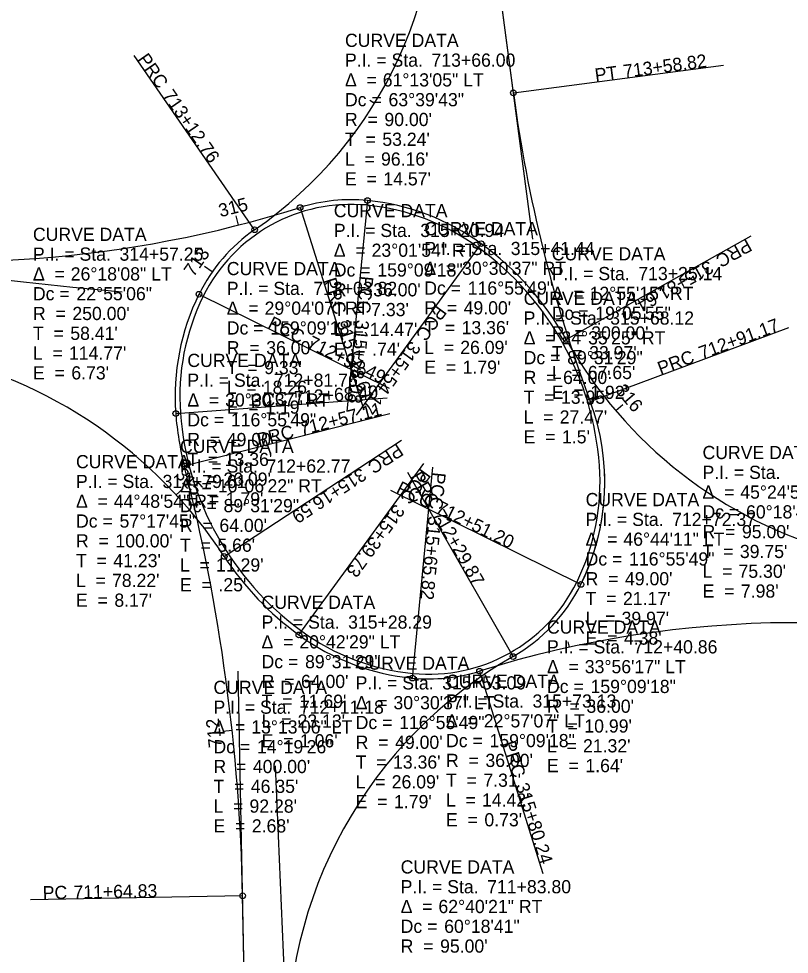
# Model space of a CAD drawing. Extents: x 2047151 to 2048731, y 456453 to 457874.
# Drawn here: x 2047586.9 to 2047750.5, y 456908.9 to 457107.4 of the extents above; entities that cross this region are included whole.
import ezdxf

# ---------------------------------------------------------------- set-up
doc = ezdxf.new("R2010")
doc.units = 0
for name, color, linetype in [('GE_P_Alignment', 7, 'Continuous'), ('GE_P_Alignment_100_Cardinal_Points', 7, 'Continuous'), ('GE_P_Alignment_100_Curve_Data', 7, 'Continuous'), ('GE_P_Alignment_100_Stations', 7, 'Continuous'), ('GE_P_Alignment_500_Cardinal_Points', 7, 'Continuous'), ('GE_P_Alignment_500_Curve_Data', 7, 'Continuous'), ('GE_P_Alignment_500_Stations', 7, 'Continuous')]:
    doc.layers.add(name, color=color, linetype=linetype)

msp = doc.modelspace()

# ---------------------------------------------------------------- linework, layer by layer
at = {"layer": 'GE_P_Alignment'}
for p, q in [((2047696.03, 457060.66), (2047679.37, 457186.67)), ((2047691.92, 457091.7), (2047681.74, 457168.72)), ((2047710.2, 457012.61), (2047710.2, 457012.61)), ((2047643.48, 456456.55), (2047633.52, 456968.93)), ((2047648.82, 456775.95), (2047641.42, 456948.9)), ((2047643.48, 456456.55), (2047634.45, 456921.29))]:
    msp.add_line(p, q, dxfattribs=at)
for centre, radius, start, end in [((2047585.83, 457136.69), 90, 304.6468, 5.8647), ((2047585.83, 457136.69), 90, 304.6468, 5.8647), ((2047717.44, 458244.57), 1200, 248.79098, 264.8083), ((2047989.34, 457131.02), 300, 187.5309, 200.4517), ((2047989.34, 457131.02), 300, 187.5309, 200.4517), ((2047571.6, 457305.84), 250, 261.1691, 287.4713), ((2047571.6, 457305.84), 250, 261.1691, 287.4713), ((2047657.47, 457033.03), 35, 84.4396, 153.7154), ((2047657.47, 457033.03), 36, 84.4396, 107.4713), ((2047657.47, 457033.03), 36, 84.4396, 107.4713), ((2047657.47, 457033.03), 36, 84.4396, 107.4713), ((2047656.21, 457020.09), 48, 53.9294, 84.4396), ((2047656.21, 457020.09), 49, 53.9294, 84.4396), ((2047656.21, 457020.09), 49, 53.9294, 84.4396), ((2047656.21, 457020.09), 49, 53.9294, 84.4396), ((2047657.47, 457033.03), 36, 124.6468, 153.7154), ((2047657.47, 457033.03), 36, 124.6468, 153.7154), ((2047657.47, 457033.03), 36, 124.6468, 153.7154), ((2047647.37, 457007.97), 64, 29.339, 53.9294), ((2047647.37, 457007.97), 64, 29.339, 53.9294), ((2047647.37, 457007.97), 64, 29.339, 53.9294), ((2047647.37, 457007.97), 63, 4.2256, 53.9294), ((2047669.12, 457027.27), 49, 153.7154, 184.2256), ((2047669.12, 457027.27), 49, 153.7154, 184.2256), ((2047669.12, 457027.27), 49, 153.7154, 184.2256), ((2047669.12, 457027.27), 48, 153.7154, 184.2256), ((2047785.98, 457085.87), 95, 209.339, 254.7532), ((2047785.98, 457085.87), 95, 209.339, 254.7532), ((2047546.89, 456938.53), 100, 33.2214, 78.0363), ((2047546.89, 456938.53), 100, 33.2214, 78.0363), ((2047662.33, 457009.07), 49, 333.7154, 20.4517), ((2047662.33, 457009.07), 49, 333.7154, 20.4517), ((2047684.08, 457028.38), 64, 184.2256, 194.3318), ((2047684.08, 457028.38), 64, 184.2256, 194.3318), ((2047684.08, 457028.38), 64, 184.2256, 194.3318), ((2047684.08, 457028.38), 63, 184.2256, 233.9294), ((2047234.52, 456913.52), 400, 1.1135, 14.3318), ((2047234.52, 456913.52), 400, 1.1135, 14.3318), ((2047662.33, 457009.07), 48, 333.7154, 4.2256), ((2047662.33, 457009.07), 49, 333.7154, 3.079), ((2047684.08, 457028.38), 64, 213.2214, 233.9294), ((2047684.08, 457028.38), 64, 213.2214, 233.9294), ((2047684.08, 457028.38), 64, 213.2214, 233.9294), ((2047673.99, 457003.32), 35, 264.4396, 333.7154), ((2047673.99, 457003.32), 36, 299.7772, 333.7154), ((2047673.99, 457003.32), 36, 299.7772, 333.7154), ((2047673.99, 457003.32), 36, 299.7772, 333.7154), ((2047752, 456754.25), 225, 73.2611, 107.3917), ((2047752, 456754.25), 225, 73.2611, 107.3917), ((2047675.25, 457016.25), 49, 233.9294, 264.4396), ((2047675.25, 457016.25), 49, 233.9294, 264.4396), ((2047675.25, 457016.25), 49, 233.9294, 264.4396), ((2047675.25, 457016.25), 48, 233.9294, 264.4396), ((2047739.05, 456889.61), 95, 119.7772, 182.4498), ((2047739.05, 456889.61), 95, 119.7772, 182.4498), ((2047673.99, 457003.32), 36, 264.4396, 287.3917), ((2047673.99, 457003.32), 36, 264.4396, 287.3917), ((2047673.99, 457003.32), 36, 264.4396, 287.3407)]:
    msp.add_arc(centre, radius, start, end, dxfattribs=at)
at = {"layer": 'GE_P_Alignment_100_Cardinal_Points'}
for p, q in [((2047637, 457062.65), (2047611.42, 457099.67)), ((2047646.66, 457067.37), (2047660.17, 457024.45)), ((2047660.95, 457068.86), (2047656.59, 457024.07)), ((2047703.17, 457039.33), (2047742.39, 457061.37)), ((2047685.06, 457059.7), (2047658.56, 457023.32)), ((2047625.19, 457048.97), (2047665.54, 457029.04)), ((2047620.26, 457023.66), (2047665.13, 457026.98)), ((2047622.07, 457012.54), (2047665.67, 457023.68)), ((2047634.45, 456921.29), (2047589.45, 456920.42))]:
    msp.add_line(p, q, dxfattribs=at)
for centre in [(2047660.95, 457068.86), (2047646.66, 457067.37), (2047637, 457062.65), (2047685.06, 457059.7), (2047625.19, 457048.97), (2047703.17, 457039.33), (2047620.26, 457023.66), (2047622.07, 457012.54), (2047634.45, 456921.29)]:
    msp.add_circle(centre, 0.6, dxfattribs=at)
at = {"layer": 'GE_P_Alignment_100_Stations'}
for p, q in [((2047662.45, 457089.47), (2047661.43, 457090.1)), ((2047633.57, 457063.64), (2047633.08, 457065.58)), ((2047681.59, 457062.01), (2047682.21, 457063.03)), ((2047628, 457053.71), (2047626.36, 457054.85)), ((2047713.65, 457024.29), (2047715.17, 457025.58)), ((2047623.77, 457005.63), (2047622.6, 457005.36)), ((2047632.22, 456956.38), (2047630.23, 456956.17))]:
    msp.add_line(p, q, dxfattribs=at)
at = {"layer": 'GE_P_Alignment_500_Cardinal_Points'}
for p, q in [((2047691.92, 457091.7), (2047736.54, 457097.6)), ((2047708.25, 457026.19), (2047750.41, 457041.92)), ((2047630.54, 456993.31), (2047668.19, 457017.97)), ((2047646.4, 456976.65), (2047672.89, 457013.02)), ((2047670.5, 456967.48), (2047674.86, 457012.27)), ((2047691.87, 456972.07), (2047669.52, 457011.13)), ((2047706.27, 456987.37), (2047665.92, 457007.3)), ((2047684.75, 456968.96), (2047698.2, 456926.02))]:
    msp.add_line(p, q, dxfattribs=at)
for centre in [(2047691.92, 457091.7), (2047708.25, 457026.19), (2047630.54, 456993.31), (2047706.27, 456987.37), (2047646.4, 456976.65), (2047691.87, 456972.07), (2047670.5, 456967.48), (2047684.75, 456968.96)]:
    msp.add_circle(centre, 0.6, dxfattribs=at)
at = {"layer": 'GE_P_Alignment_500_Stations'}
for p, q in [((2047705.28, 457034.52), (2047704.14, 457034.13)), ((2047620.34, 457006.38), (2047621.81, 457007.74)), ((2047703.84, 456974.03), (2047703.59, 456975.2)), ((2047668.68, 456953.43), (2047667.79, 456954.24))]:
    msp.add_line(p, q, dxfattribs=at)

# ---------------------------------------------------------------- texts
at = {"layer": 'GE_P_Alignment_100_Cardinal_Points'}
for s, rotation, p in [('PRC', 304.6468, (2047612.03, 457098.86)), ('713+12.76', 304.6468, (2047617.34, 457091.17)), ('PRC', 209.339, (2047741.5, 457060.82)), ('315+81.64', 209.339, (2047733.35, 457056.24)), ('PRC', 287.4713, (2047651.56, 457051.95)), ('PCC', 264.4396, (2047659.45, 457052.92)), ('PCC', 233.9294, (2047675.7, 457046.78)), ('PCC', 333.7154, (2047639.59, 457041.91)), ('315+13.61', 287.4713, (2047654.37, 457043.03)), ('315+28.08', 264.4396, (2047658.54, 457043.61)), ('712+94.49', 333.7154, (2047647.97, 457037.77)), ('315+54.17', 233.9294, (2047670.2, 457039.22)), ('712+68.40', 4.2256, (2047645.54, 457025.58)), ('PCC', 4.2256, (2047636.22, 457024.89)), ('712+57.11', 14.3318, (2047646.94, 457018.94)), ('PRC', 14.3318, (2047637.88, 457016.62)), ('PC', 1.1135, (2047592.04, 456920.52)), ('711+64.83', 1.1135, (2047598.56, 456920.64))]:
    msp.add_text(s, height=2.8, rotation=rotation, dxfattribs=at).set_placement(p)
at = {"layer": 'GE_P_Alignment_100_Curve_Data'}
for s, p in [('CURVE DATA', (2047656.18, 457101.46)), ('P.I. = Sta. ', (2047656.18, 457097.26)), ('713+66.00', (2047674.55, 457097.26)), ('Δ  = ', (2047656.18, 457093.06)), ('61°13\'05" LT', (2047664.2, 457093.06)), ('Dc = ', (2047656.18, 457088.86)), ('63°39\'43"', (2047665.42, 457088.86)), ('R  = ', (2047656.18, 457084.66)), ("90.00'", (2047664.55, 457084.66)), ('T  = ', (2047656.18, 457080.46)), ("53.24'", (2047664.11, 457080.46)), ('L  = ', (2047656.18, 457076.26)), ("96.16'", (2047663.83, 457076.26)), ('E  = ', (2047656.18, 457072.06)), ("14.57'", (2047664.33, 457072.06)), ('CURVE DATA', (2047653.81, 457065.31)), ('P.I. = Sta. ', (2047653.81, 457061.11)), ('315+20.94', (2047672.17, 457061.11)), ('CURVE DATA', (2047673.01, 457061.48)), ('CURVE DATA', (2047589.94, 457060.28)), ('Δ  = ', (2047653.81, 457056.91)), ('23°01\'54" RT', (2047661.83, 457056.91)), ('P.I. = Sta. ', (2047673.01, 457057.28)), ('315+41.44', (2047691.37, 457057.28)), ('P.I. = Sta. ', (2047589.94, 457056.08)), ('314+57.25', (2047608.31, 457056.08)), ('CURVE DATA', (2047631.09, 457053.01)), ('Dc = ', (2047653.81, 457052.71)), ('159°09\'18"', (2047663.05, 457052.71)), ('Δ  = ', (2047673.01, 457053.08)), ('30°30\'37" RT', (2047681.03, 457053.08)), ('Δ  = ', (2047589.94, 457051.88)), ('26°18\'08" LT', (2047597.96, 457051.88)), ('P.I. = Sta. ', (2047631.09, 457048.81)), ('713+03.82', (2047649.46, 457048.81)), ('R  = ', (2047653.81, 457048.51)), ("36.00'", (2047662.17, 457048.51)), ('Dc = ', (2047673.01, 457048.88)), ('116°55\'49"', (2047682.24, 457048.88)), ('Dc = ', (2047589.94, 457047.68)), ('22°55\'06"', (2047599.18, 457047.68)), ('CURVE DATA', (2047694.11, 457046.71)), ('Δ  = ', (2047631.09, 457044.61)), ('29°04\'07" RT', (2047639.12, 457044.61)), ('R  = ', (2047673.01, 457044.68)), ("49.00'", (2047681.37, 457044.68)), ('R  = ', (2047589.94, 457043.48)), ("250.00'", (2047598.31, 457043.48)), ('T  = ', (2047653.81, 457044.31)), ("7.33'", (2047661.74, 457044.31)), ('P.I. = Sta. ', (2047694.11, 457042.51)), ('315+68.12', (2047712.48, 457042.51)), ("13.36'", (2047680.94, 457040.48)), ('T  = ', (2047589.94, 457039.28)), ("58.41'", (2047597.87, 457039.28)), ('Dc = ', (2047631.09, 457040.41)), ('159°09\'18"', (2047640.33, 457040.41)), ('L  = ', (2047653.81, 457040.11)), ("14.47'", (2047661.45, 457040.11)), ('T  = ', (2047673.01, 457040.48)), ('Δ  = ', (2047694.11, 457038.31)), ('24°35\'25" RT', (2047702.13, 457038.31)), ('L  = ', (2047589.94, 457035.08)), ("114.77'", (2047597.59, 457035.08)), ('R  = ', (2047631.09, 457036.21)), ("36.00'", (2047639.46, 457036.21)), ('E  = ', (2047653.81, 457035.91)), (".74'", (2047661.96, 457035.91)), ('L  = ', (2047673.01, 457036.28)), ("26.09'", (2047680.65, 457036.28)), ('CURVE DATA', (2047622.72, 457033.52)), ('Dc = ', (2047694.11, 457034.11)), ('89°31\'29"', (2047703.35, 457034.11)), ('E  = ', (2047589.94, 457030.88)), ("6.73'", (2047598.09, 457030.88)), ('T  = ', (2047631.09, 457032.01)), ("9.33'", (2047639.03, 457032.01)), ('E  = ', (2047673.01, 457032.08)), ("1.79'", (2047681.16, 457032.08)), ('P.I. = Sta. ', (2047622.72, 457029.32)), ('712+81.76', (2047641.09, 457029.32)), ('R  = ', (2047694.11, 457029.91)), ("64.00'", (2047702.48, 457029.91)), ('L  = ', (2047631.09, 457027.81)), ("18.26'", (2047638.74, 457027.81)), ('Δ  = ', (2047622.72, 457025.12)), ('30°30\'37" RT', (2047630.74, 457025.12)), ('T  = ', (2047694.11, 457025.71)), ("13.95'", (2047702.04, 457025.71)), ('E  = ', (2047631.09, 457023.61)), ("1.19'", (2047639.25, 457023.61)), ('Dc = ', (2047622.72, 457020.92)), ('116°55\'49"', (2047631.96, 457020.92)), ('L  = ', (2047694.11, 457021.51)), ("27.47'", (2047701.76, 457021.51)), ('R  = ', (2047622.72, 457016.72)), ("49.00'", (2047631.09, 457016.72)), ('E  = ', (2047694.11, 457017.31)), ("1.5'", (2047702.26, 457017.31)), ('CURVE DATA', (2047621.16, 457015.3)), ('CURVE DATA', (2047732.08, 457013.97)), ('P.I. = Sta. ', (2047621.16, 457011.1)), ('T  = ', (2047622.72, 457012.52)), ("13.36'", (2047630.65, 457012.52)), ('712+62.77', (2047639.53, 457011.1)), ('P.I. = Sta. ', (2047732.08, 457009.77)), ('Δ  = ', (2047621.16, 457006.9)), ('L  = ', (2047622.72, 457008.32)), ('10°06\'22" RT', (2047629.19, 457006.9)), ("26.09'", (2047630.37, 457008.32)), ('Δ  = ', (2047732.08, 457005.57)), ('45°24\'51" LT', (2047740.1, 457005.57)), ('E  = ', (2047622.72, 457004.12)), ("1.79'", (2047630.87, 457004.12)), ('Dc = ', (2047621.16, 457002.7)), ('89°31\'29"', (2047630.4, 457002.7)), ('Dc = ', (2047732.08, 457001.37)), ('60°18\'41"', (2047741.32, 457001.37)), ('R  = ', (2047621.16, 456998.5)), ("64.00'", (2047629.53, 456998.5)), ('R  = ', (2047732.08, 456997.17)), ("95.00'", (2047740.45, 456997.17)), ('T  = ', (2047621.16, 456994.3)), ("5.66'", (2047629.1, 456994.3)), ('T  = ', (2047732.08, 456992.97)), ("39.75'", (2047740.01, 456992.97)), ('L  = ', (2047621.16, 456990.1)), ("11.29'", (2047628.81, 456990.1)), ('L  = ', (2047732.08, 456988.77)), ("75.30'", (2047739.73, 456988.77)), ('E  = ', (2047621.16, 456985.9)), (".25'", (2047629.32, 456985.9)), ('E  = ', (2047732.08, 456984.57)), ("7.98'", (2047740.23, 456984.57)), ('CURVE DATA', (2047628.26, 456964.12)), ('P.I. = Sta. ', (2047628.26, 456959.92)), ('712+11.18', (2047646.63, 456959.92)), ('Δ  = ', (2047628.26, 456955.72)), ('13°13\'06" LT', (2047636.28, 456955.72)), ('Dc = ', (2047628.26, 456951.52)), ('14°19\'26"', (2047637.5, 456951.52)), ('R  = ', (2047628.26, 456947.32)), ("400.00'", (2047636.63, 456947.32)), ('T  = ', (2047628.26, 456943.12)), ("46.35'", (2047636.19, 456943.12)), ('L  = ', (2047628.26, 456938.92)), ("92.28'", (2047635.91, 456938.92)), ('E  = ', (2047628.26, 456934.72)), ("2.68'", (2047636.41, 456934.72))]:
    msp.add_text(s, height=2.8, dxfattribs=at).set_placement(p)
at = {"layer": 'GE_P_Alignment_100_Stations'}
for s, rotation, p in [('315', 14.3528, (2047629.75, 457065.29)), ('713', 54.9481, (2047624.04, 457052.5)), ('316', 310.4129, (2047713.46, 457028.44)), ('712', 96.1514, (2047630.08, 456952.86))]:
    msp.add_text(s, height=2.8, rotation=rotation, dxfattribs=at).set_placement(p)
at = {"layer": 'GE_P_Alignment_500_Cardinal_Points'}
for s, rotation, p in [('713+58.82', 7.5309, (2047715.45, 457094.86)), ('PT', 7.5309, (2047709.41, 457094.06)), ('712+91.17', 20.4517, (2047731.94, 457035.08)), ('PRC', 20.4517, (2047723.18, 457031.81)), ('PRC', 213.2214, (2047667.34, 457017.36)), ('315+16.59', 213.2214, (2047659.52, 457012.24)), ('PCC', 233.9294, (2047672.33, 457012.16)), ('PRC', 299.7772, (2047670.03, 457010.32)), ('PCC', 264.4396, (2047674.81, 457011.26)), ('PCC', 333.7154, (2047666.85, 457006.89)), ('315+39.73', 233.9294, (2047666.82, 457004.61)), ('712+51.20', 333.7154, (2047675.23, 457002.76)), ('315+65.82', 264.4396, (2047673.9, 457001.95)), ('712+29.87', 299.7772, (2047674.68, 457002.21)), ('PRC', 287.3917, (2047689.59, 456953.66)), ('315+80.24', 287.3917, (2047692.39, 456944.74))]:
    msp.add_text(s, height=2.8, rotation=rotation, dxfattribs=at).set_placement(p)
at = {"layer": 'GE_P_Alignment_500_Curve_Data'}
for s, p in [('CURVE DATA', (2047700.08, 457056.15)), ('P.I. = Sta. ', (2047700.08, 457051.95)), ('713+25.14', (2047718.45, 457051.95)), ('Δ  = ', (2047700.08, 457047.75)), ('12°55\'15" RT', (2047708.11, 457047.75)), ('Dc = ', (2047700.08, 457043.55)), ('19°05\'55"', (2047709.32, 457043.55)), ('R  = ', (2047700.08, 457039.35)), ("300.00'", (2047708.45, 457039.35)), ('T  = ', (2047700.08, 457035.15)), ("33.97'", (2047708.02, 457035.15)), ('L  = ', (2047700.08, 457030.95)), ("67.65'", (2047707.73, 457030.95)), ('E  = ', (2047700.08, 457026.75)), ("1.92'", (2047708.24, 457026.75)), ('CURVE DATA', (2047599.08, 457012.03)), ('P.I. = Sta. ', (2047599.08, 457007.83)), ('314+79.61', (2047617.45, 457007.83)), ('Δ  = ', (2047599.08, 457003.63)), ('44°48\'54" RT', (2047607.1, 457003.63)), ('CURVE DATA', (2047707.26, 457003.98)), ('Dc = ', (2047599.08, 456999.43)), ('57°17\'45"', (2047608.32, 456999.43)), ('P.I. = Sta. ', (2047707.26, 456999.78)), ('712+72.37', (2047725.63, 456999.78)), ('R  = ', (2047599.08, 456995.23)), ("100.00'", (2047607.45, 456995.23)), ('Δ  = ', (2047707.26, 456995.58)), ('46°44\'11" LT', (2047715.28, 456995.58)), ('T  = ', (2047599.08, 456991.03)), ("41.23'", (2047607.01, 456991.03)), ('Dc = ', (2047707.26, 456991.38)), ('116°55\'49"', (2047716.5, 456991.38)), ("78.22'", (2047606.72, 456986.83)), ('R  = ', (2047707.26, 456987.18)), ("49.00'", (2047715.62, 456987.18)), ('L  = ', (2047599.08, 456986.83)), ('T  = ', (2047707.26, 456982.98)), ("21.17'", (2047715.19, 456982.98)), ('E  = ', (2047599.08, 456982.63)), ("8.17'", (2047607.23, 456982.63)), ('CURVE DATA', (2047638.47, 456982.18)), ('P.I. = Sta. ', (2047638.47, 456977.98)), ('315+28.29', (2047656.84, 456977.98)), ('CURVE DATA', (2047699.07, 456976.92)), ('L  = ', (2047707.26, 456978.78)), ("39.97'", (2047714.9, 456978.78)), ('Δ  = ', (2047638.47, 456973.78)), ('20°42\'29" LT', (2047646.49, 456973.78)), ('E  = ', (2047707.26, 456974.58)), ("4.38'", (2047715.41, 456974.58)), ('P.I. = Sta. ', (2047699.07, 456972.72)), ('712+40.86', (2047717.44, 456972.72)), ('Dc = ', (2047638.47, 456969.58)), ('89°31\'29"', (2047647.71, 456969.58)), ('CURVE DATA', (2047658.45, 456969.27)), ('Δ  = ', (2047699.07, 456968.52)), ('33°56\'17" LT', (2047707.09, 456968.52)), ('R  = ', (2047638.47, 456965.38)), ("64.00'", (2047646.84, 456965.38)), ('P.I. = Sta. ', (2047658.45, 456965.07)), ('315+53.09', (2047676.82, 456965.07)), ('CURVE DATA', (2047677.63, 456965.42)), ('Dc = ', (2047699.07, 456964.32)), ('159°09\'18"', (2047708.31, 456964.32)), ('T  = ', (2047638.47, 456961.18)), ("11.69'", (2047646.4, 456961.18)), ('P.I. = Sta. ', (2047677.63, 456961.22)), ('315+73.13', (2047695.99, 456961.22)), ('Δ  = ', (2047658.45, 456960.87)), ('30°30\'37" LT', (2047666.47, 456960.87)), ('R  = ', (2047699.07, 456960.12)), ("36.00'", (2047707.44, 456960.12)), ('L  = ', (2047638.47, 456956.98)), ("23.13'", (2047646.12, 456956.98)), ('Dc = ', (2047658.45, 456956.67)), ('116°55\'49"', (2047667.69, 456956.67)), ('Δ  = ', (2047677.63, 456957.02)), ('22°57\'07" LT', (2047685.65, 456957.02)), ('T  = ', (2047699.07, 456955.92)), ("10.99'", (2047707, 456955.92)), ('E  = ', (2047638.47, 456952.78)), ("1.06'", (2047646.62, 456952.78)), ('R  = ', (2047658.45, 456952.47)), ("49.00'", (2047666.82, 456952.47)), ('Dc = ', (2047677.63, 456952.82)), ('159°09\'18"', (2047686.86, 456952.82)), ('L  = ', (2047699.07, 456951.72)), ("21.32'", (2047706.71, 456951.72)), ('T  = ', (2047658.45, 456948.27)), ("13.36'", (2047666.38, 456948.27)), ('R  = ', (2047677.63, 456948.62)), ("36.00'", (2047685.99, 456948.62)), ('E  = ', (2047699.07, 456947.52)), ("1.64'", (2047707.22, 456947.52)), ('L  = ', (2047658.45, 456944.07)), ("26.09'", (2047666.1, 456944.07)), ('T  = ', (2047677.63, 456944.42)), ("7.31'", (2047685.56, 456944.42)), ('E  = ', (2047658.45, 456939.87)), ("1.79'", (2047666.6, 456939.87)), ('L  = ', (2047677.63, 456940.22)), ("14.42'", (2047685.27, 456940.22)), ('E  = ', (2047677.63, 456936.02)), ("0.73'", (2047685.78, 456936.02)), ('CURVE DATA', (2047668, 456926.01)), ('P.I. = Sta. ', (2047668, 456921.81)), ('711+83.80', (2047686.37, 456921.81)), ('Δ  = ', (2047668, 456917.61)), ('62°40\'21" RT', (2047676.02, 456917.61)), ('Dc = ', (2047668, 456913.41)), ('60°18\'41"', (2047677.24, 456913.41)), ('R  = ', (2047668, 456909.21)), ("95.00'", (2047676.37, 456909.21))]:
    msp.add_text(s, height=2.8, dxfattribs=at).set_placement(p)
at = {"layer": 'GE_P_Alignment_500_Stations'}
msp.add_text('315', height=2.8, rotation=312.7291, dxfattribs=at).set_placement((2047619.98, 457010.53))

doc.saveas('drawing.dxf')
